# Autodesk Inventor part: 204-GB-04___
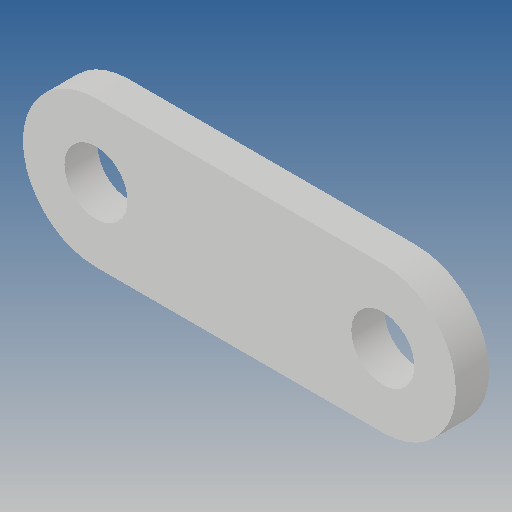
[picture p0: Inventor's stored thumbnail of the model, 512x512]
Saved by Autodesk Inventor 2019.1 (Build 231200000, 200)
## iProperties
Created: 2010-06
Part Number: 204-GB-04___
Material: Ogólny
Document SubType Name: Modeling
Designer: CADENGINEERING4
Density: 1 g/cm^3
Appearance: Domyślna
Author: CADENGINEERING4
Revision Number: ANY
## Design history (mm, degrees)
feature "NONE"
node "Bryła1"
